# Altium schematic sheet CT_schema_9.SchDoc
size 277 x 170 mm
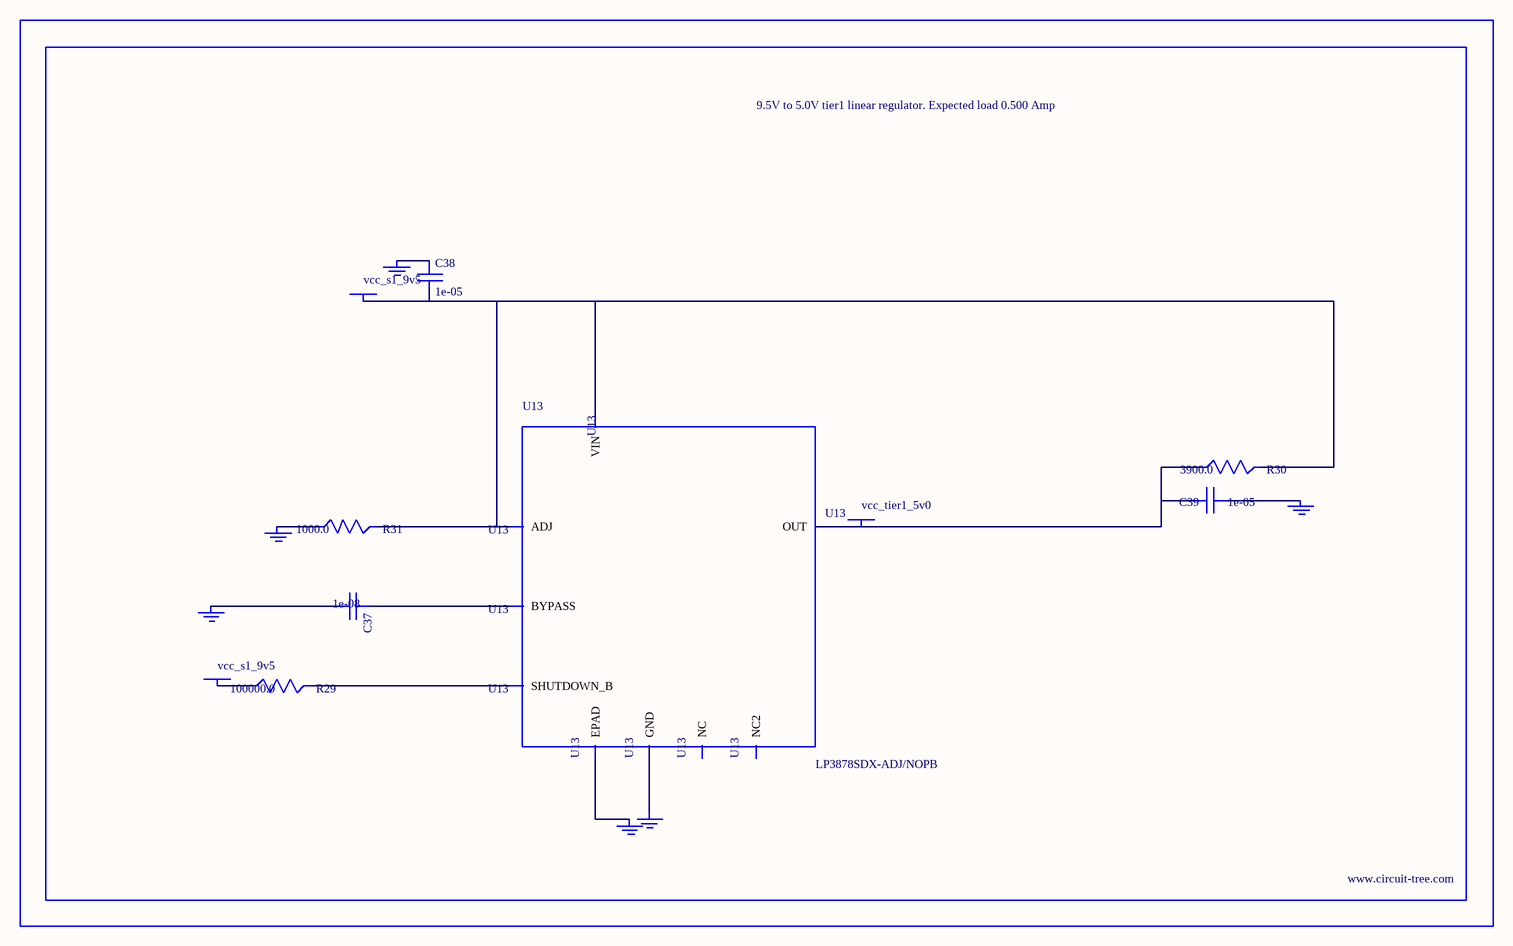
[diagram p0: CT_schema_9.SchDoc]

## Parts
BORDER8  (no value)
C37  1e-08  [C0402]
C38  1e-05  [C1206]
C39  1e-05  [C1210]
GND_INSTANCE_8_0  (no value)
GND_INSTANCE_8_1  (no value)
GND_INSTANCE_8_2  (no value)
GND_INSTANCE_8_3  (no value)
GND_INSTANCE_8_4  (no value)
GND_INSTANCE_8_5  (no value)
POWER_INSTANCE_8_0  vcc_s1_9v5
POWER_INSTANCE_8_1  vcc_s1_9v5
POWER_INSTANCE_8_2  vcc_tier1_5v0
R29  100000.0  [R0603]
R30  3900.0  [R0603]
R31  1000.0  [R0603]
U13  LP3878SDX-ADJ/NOPB  [WSON-8]

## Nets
NetC37_1: C37.1 U13.1(BYPASS)
NetC37_2: C37.2 GND_INSTANCE_8_0.0(GND)
NetC38_1: C38.1 GND_INSTANCE_8_1.0(GND)
NetC38_2: C38.2 POWER_INSTANCE_8_0.0(PWR) R30.2 R31.2 U13.4(VIN) U13.6(ADJ)
NetC39_1: C39.1 GND_INSTANCE_8_2.0(GND)
NetC39_2: C39.2 POWER_INSTANCE_8_2.0(PWR) R30.1 U13.5(OUT)
NetGND_INSTANCE_8_3_0: GND_INSTANCE_8_3.0(GND) R31.1
NetGND_INSTANCE_8_4_0: GND_INSTANCE_8_4.0(GND) U13.PAD(EPAD)
NetGND_INSTANCE_8_5_0: GND_INSTANCE_8_5.0(GND) U13.3(GND)
NetPOWER_INSTANCE_8_1_0: POWER_INSTANCE_8_1.0(PWR) R29.1
NetR29_2: R29.2 U13.8(SHUTDOWN_B)

Not connected (* = marked no-connect by the designer): U13 2(NC) 7(NC2)

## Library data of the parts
BORDER8 = BORDER_PAGE8
C37 = C0402C103K3RAC
C38 = C1206C106K3RACTU
C39 = GRM32DR61E106MA12L
GND_INSTANCE_8_0-GND_INSTANCE_8_5 = GND
POWER_INSTANCE_8_0-POWER_INSTANCE_8_2 = PWR
R29 = RC0603JR-07100KL
R30 = RC0603JR-073K9L
R31 = RC0603JR-071KL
